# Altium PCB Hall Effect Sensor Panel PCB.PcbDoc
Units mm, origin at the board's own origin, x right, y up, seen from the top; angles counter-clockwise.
Board outline 358 x 45 mm, 2 copper layers (Top Layer, Bottom Layer); 37 components, 42 nets, 131 pads, 19 vias.
Unrouted connection lines stored in the file: 1.
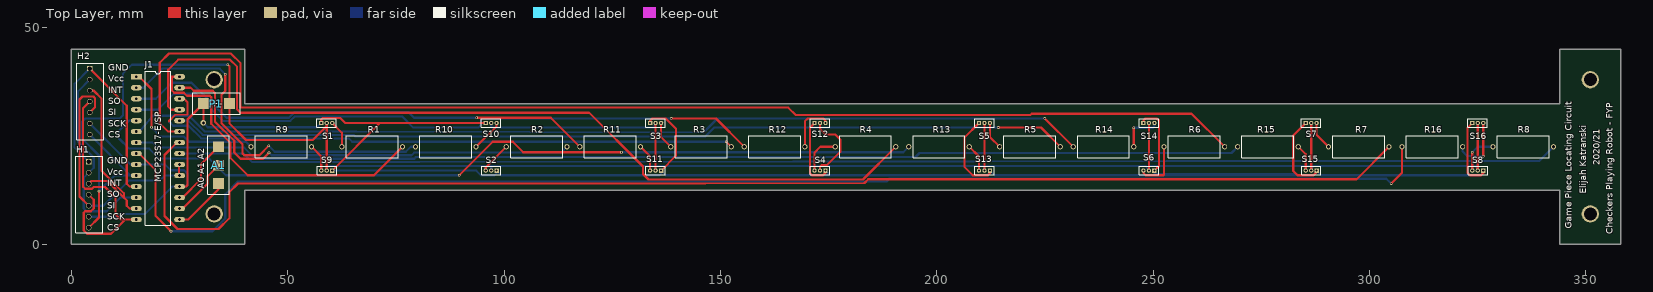
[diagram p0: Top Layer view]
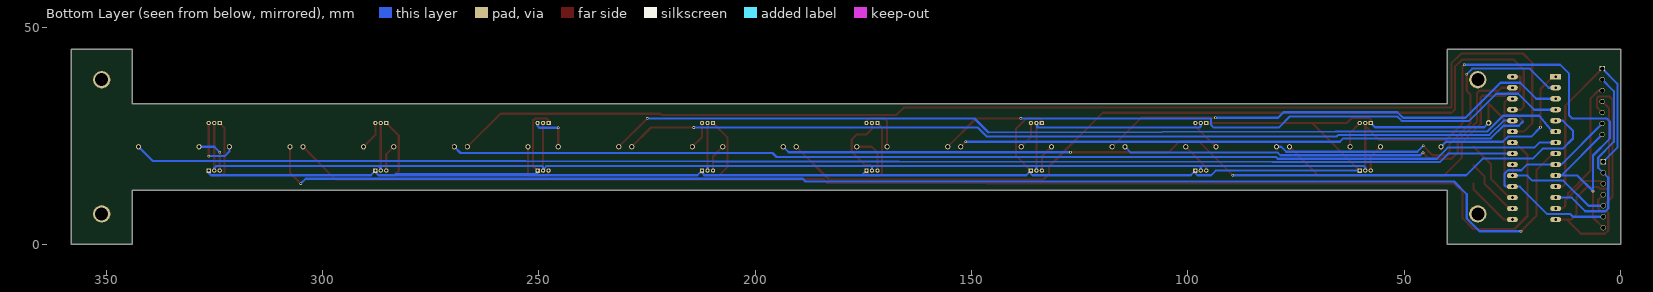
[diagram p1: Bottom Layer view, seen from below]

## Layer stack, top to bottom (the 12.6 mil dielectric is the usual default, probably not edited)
Top Solder: solder mask 0.0102, Solder Resist, Dk 3.5
Top Layer: signal copper 0.0356
Dielectric 1: dielectric 0.32, FR-4, Dk 4.8
Bottom Layer: signal copper 0.0356
Bottom Solder: solder mask 0.0102, Solder Resist, Dk 3.5

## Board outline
344,32.5 344,45 358,45 358,0 344,0 344,12.5 40,12.5 40,0 0,0 0,45 40,45 40,32.5

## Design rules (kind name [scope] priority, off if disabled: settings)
Clearance [All] p1: gap=0.13 ignorepadtopadclearanceinfootprint=FALSE
PolygonConnect [All] p1: connectstyle=Relief reliefconductorwidth=0.254 reliefentries=4 polygonreliefangle="90 Angle" airgapwidth=0.254
RoutingVias [All] p1: holewidth=0.3 width=0.6 viastyle="Through Hole" minholewidth=0.3 minwidth=0.6 maxholewidth=0.3 maxwidth=0.6
SolderMaskExpansion [All] p1: expansion=0.102 istentingtop=FALSE
Width [All] p1: maxlimit=1 minlimit=0.3 preferedwidth=0.5
30 further rules are at their usual default settings.

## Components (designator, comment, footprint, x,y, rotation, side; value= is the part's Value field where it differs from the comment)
A1 "Address" ADDRESS 34,17 r90 top
H1 "1x7 Header" MOLEX 4,19.04 r0 top
H2 "1x7 Header" MOLEX 4.24,40.58 r0 top
J1 "16-Bit I/O Expander" MCP23S17-E/SP 15,38.7 r0 top
P1 "Power" POWER 33.5,32.5 r0 top
R1 "4k7R" CFR100J4K7 76.5,22.5 r180 top
R2 "4k7R" CFR100J4K7 114.5,22.5 r180 top
R3 "4k7R" CFR100J4K7 152.5,22.5 r180 top
R4 "4k7R" CFR100J4K7 190.5,22.5 r180 top
R5 "4k7R" CFR100J4K7 228.5,22.5 r180 top
R6 "4k7R" CFR100J4K7 266.5,22.5 r180 top
R7 "4k7R" CFR100J4K7 304.5,22.5 r180 top
R8 "4k7R" CFR100J4K7 342.5,22.5 r180 top
R9 "4k7R" CFR100J4K7 55.5,22.5 r180 top
R10 "4k7R" CFR100J4K7 93.5,22.5 r180 top
R11 "4k7R" CFR100J4K7 131.5,22.5 r180 top
R12 "4k7R" CFR100J4K7 169.5,22.5 r180 top
R13 "4k7R" CFR100J4K7 207.5,22.5 r180 top
R14 "4k7R" CFR100J4K7 245.5,22.5 r180 top
R15 "4k7R" CFR100J4K7 283.5,22.5 r180 top
R16 "4k7R" CFR100J4K7 321.5,22.5 r180 top
S1 "Hall Effect Sensor" A1104EUA-T 57.73,28 r90 top
S2 "Hall Effect Sensor" A1104EUA-T 98.27,17 r270 top
S3 "Hall Effect Sensor" A1104EUA-T 133.73,28 r90 top
S4 "Hall Effect Sensor" A1104EUA-T 174.27,17 r270 top
S5 "Hall Effect Sensor" A1104EUA-T 209.73,28 r90 top
S6 "Hall Effect Sensor" A1104EUA-T 250.27,17 r270 top
S7 "Hall Effect Sensor" A1104EUA-T 285.23,28 r90 top
S8 "Hall Effect Sensor" A1104EUA-T 326.27,17 r270 top
S9 "Hall Effect Sensor" A1104EUA-T 60.27,17 r270 top
S10 "Hall Effect Sensor" A1104EUA-T 95.73,28 r90 top
S11 "Hall Effect Sensor" A1104EUA-T 136.27,17 r270 top
S12 "Hall Effect Sensor" A1104EUA-T 171.73,28 r90 top
S13 "Hall Effect Sensor" A1104EUA-T 212.27,17 r270 top
S14 "Hall Effect Sensor" A1104EUA-T 247.73,28 r90 top
S15 "Hall Effect Sensor" A1104EUA-T 287.77,17 r270 top
S16 "Hall Effect Sensor" A1104EUA-T 323.73,28 r90 top

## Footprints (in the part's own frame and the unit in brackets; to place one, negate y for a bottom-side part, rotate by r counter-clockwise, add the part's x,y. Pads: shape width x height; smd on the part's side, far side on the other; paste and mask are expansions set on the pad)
A1104EUA-T [mm]
  rect 1x1 hole 0.5: 1(0,0)
  round 1 hole 0.5: 2(0,-1.27) 3(0,-2.54)
  silkscreen extent -1,-3.5 1,1
ADDRESS [mm]
  rect 2.5x2.5 smd: 1(-3,0) 2(1.25,0) 3(5.5,0)
  silkscreen extent -5.5,-2.5 8,2.5
CFR100J4K7 [mm]
  round 1.2 hole 0.76: 1(0,0) 2(14,0)
  silkscreen extent 1,-2.5 13,2.5
MCP23S17-E/SP [mm]
  rect 2.5x1.2 hole 0.65: 1(0,0)
  oval 2.5x1.2 hole 0.65: 2(0,-2.54) 3(0,-5.08) 4(0,-7.62) 5(0,-10.16) 6(0,-12.7) 7(0,-15.24) 8(0,-17.78) 9(0,-20.32) 10(0,-22.86) 11(0,-25.4) 12(0,-27.94) 13(0,-30.48) 14(0,-33.02) 15(10,-33.02) 16(10,-30.48) 17(10,-27.94) 18(10,-25.4) 19(10,-22.86) 20(10,-20.32) 21(10,-17.78) 22(10,-15.24) 23(10,-12.7) 24(10,-10.16) 25(10,-7.62) 26(10,-5.08) 27(10,-2.54) 28(10,0)
  silkscreen extent 2.09,-34.29 7.92,1.27
MOLEX [mm]
  rect 1.2x1.2 hole 1.02: 1(0,0)
  round 1.2 hole 1.02: 2(0,-2.54) 3(0,-5.08) 4(0,-7.62) 5(0,-10.16) 6(0,-12.7) 7(0,-15.24)
  silkscreen extent -3.02,-16.4 3.22,1.23
POWER [mm]
  rect 2.5x2.5 smd: 1(-3,0) 2(3,0)
  silkscreen extent -5.5,-2.5 5.5,2.5

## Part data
H1 H2: library part 22-23-2071, "CONN HEADER VERT 7POS 2.54MM", Color=White, Contact Resistance=10mR, Current Rating=4A, Flammability Rating="UL94 V-0", Insulation Resistance=500GR, Manufacturer=Molex, Max Current Rating=10A, Max Operating Temperature=75°C, Max Voltage Rating (AC)=250V, Min Operating Temperature=0°C, Package Quantity=4000, Supplier Part Number 1=6795603P
J1: library part MCP23S17-E/SP, "TE CONNECTIVITY         CFR100J4K7             Through Hole Resistor, 4.7 kohm, 500 V, Axial Leaded, 1 W,  5%, CFR Series", Case/Package=PDIP, Frequency=10MHz, Manufacturer=Microchip, Max Operating Temperature=125°C, Max Supply Voltage=5.5V, Min Operating Temperature=-40°C, Min Supply Voltage=1.8V, Nominal Supply Current=1mA, Supplier Part Number 1=9126833
R1 R2 R3 R4 R5 R6 R7 R8 R9 R10 R11 R12 R13 R14 R15 R16: library part CFR100J4K7, "TE CONNECTIVITY         CFR100J4K7             Through Hole Resistor, 4.7 kohm, 500 V, Axial Leaded, 1 W,  5%, CFR Series", Case/Package=Conformal, Manufacturer="TE Connectivity", Max Operating Temperature=155°C, Min Operating Temperature=-55°C, Number of Resistors=1, Power Rating=1W, Resistance=4.7kR, Resistor Type="Thin Film", Supplier Part Number 1=0131873, Temperature Coefficient=0ppm/°C, Tolerance=5%, Voltage Rating=500V
S1 S2 S3 S4 S5 S6 S7 S8 S9 S10 S11 S12 S13 S14 S15 S16: library part A1104EUA-T, "ALLEGRO MICROSYSTEMS - A1104EUA-T - IC, HALL-EFFECT SWITCH SIP-3", Case/Package=SIP, Manufacturer="Allegro MicroSystems", Max Operating Temperature=85°C, Max Output Current=25mA, Max Supply Current=7.5mA, Max Supply Voltage=24V, Min Operating Temperature=-40°C, Min Supply Voltage=3.8V, Package Quantity=4000, Supplier Part Number 1=6807488

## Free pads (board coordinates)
  round 4 hole 3: 1(33,38) 2(33,7) 3(351,38) 4(351,7)

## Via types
v1: diameter 0.6, hole 0.3, Top Layer to Bottom Layer, 18 vias
v2: diameter 1.27, hole 0.711, Top Layer to Bottom Layer, 1 vias

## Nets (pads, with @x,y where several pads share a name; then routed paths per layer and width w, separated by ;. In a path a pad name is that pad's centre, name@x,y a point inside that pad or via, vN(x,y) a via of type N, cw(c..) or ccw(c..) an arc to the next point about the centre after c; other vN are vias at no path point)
GND: H1.7 H2.7 J1.10 P1.2 S1.2 S2.2 S3.2 S4.2 S5.2 S6.2 S7.2 S8.2 S9.2 S10.2 S11.2 S12.2 S13.2 S14.2 S15.2 S16.2 | length 531.9
  Top Layer w0.5: H1.7 6.375,6.175 v1(6.375,12.268) ; v1(36.144,41.478) 36.5,41.122 P1.2 36.5,27.929 40.35,24.079 55.774,24.079 59,27.305 ; S9.2 59,27.305 ; S1.2 59,27.305 ; S11.2 S3.2 ; S4.2 173,17.908 173.355,18.263 174.574,18.263 177.673,21.361 177.673,24.181 176.53,25.324 174.346,25.324 173,26.67 S12.2 ; S13.2 S5.2 ; S6.2 S14.2 ; S15.2 S7.2 ; S8.2 S16.2
  Bottom Layer w0.5: H2.7 13.74,15.84 ; J1.10 13.74,15.84 ; v1(36.144,41.478) 13.97,41.478 11.887,39.395 11.887,29.718 11.199,29.03 3.175,29.03 2.495,28.35 2.495,24.383 6.375,20.502 v1(6.375,12.268) 9.947,15.84 13.74,15.84 ; S9.2 59,17.687 59.372,18.059 97,18.059 ; S2.2 97,18.059 ; S10.2 97,27.181 97.231,26.949 134.798,26.949 134.798,27.798 S3.2 ; S11.2 135,18.059 ; S4.2 173,18.059 ; S13.2 210.959,17.087 210.959,18.059 ; S15.2 286.5,17.539 287.02,18.059 ; S8.2 325,17.544 324.485,18.059 287.02,18.059 ; 97,18.059 135,18.059 ; 135,18.059 173,18.059 ; 173,18.059 210.959,18.059 ; 210.959,18.059 248.285,18.059 S6.2 249,17.86 249.199,18.059 287.02,18.059
NetA1_1: A1.1 J1.15 | length 13.2
  Top Layer w0.5: J1.15 26.98,5.68 34,12.7 A1.1
NetA1_2: A1.2 J1.16 | length 14.1
  Top Layer w0.5: J1.16 25.654,8.22 31.471,14.037 31.471,15.721 A1.2
NetA1_3: A1.3 J1.17 | length 15.9
  Top Layer w0.5: J1.17 25.654,10.76 29.921,15.027 29.921,18.421 A1.3
NetH1_1: H1.1 H2.1 J1.11 | length 57
  Top Layer w0.5: H2.1 12.802,32.018 12.802,13.97 13.472,13.3 J1.11
  Bottom Layer w0.5: H1.1 0.737,22.303 0.737,37.077 H2.1
NetH1_2: H1.2 H2.2 J1.12 | length 47.1
  Bottom Layer w0.5: H2.2 1.549,35.349 1.549,23.647 5.156,20.041 5.156,17.656 H1.2 2.845,15.345 2.845,8.255 3.48,7.62 8.153,7.62 11.293,10.76 J1.12
NetH1_3: H1.3 H2.3 J1.13 | length 43.1
  Top Layer w0.5: H1.3 4.62,14.58 8.331,14.58 12.116,10.795 ; H2.3 5.08,35.5 6.985,33.595 6.985,16.916 12.116,11.786 12.116,10.795 ; J1.13 13.456,8.22 12.786,8.89 12.786,10.125 12.116,10.795
NetH1_4: H1.4 H2.4 J1.14 | length 60.1
  Top Layer w0.5: H1.4 5.156,10.264 5.156,8.255 4.496,7.595 3.175,7.595 2.845,7.264 2.845,3.175 3.632,2.388 9.128,2.388 12.421,5.68 ; H2.4 2.692,31.412 2.692,13.284 3.175,12.802 4.763,12.802 5.182,13.221 7.774,13.221 10.16,10.834 10.16,6.95 11.43,5.68 12.421,5.68 ; J1.14 12.421,5.68
NetH1_5: H1.5 H2.5 J1.19 J1.20 | length 60
  Top Layer w0.5: H1.5 1.88,11 1.88,33.45 2.54,34.11 5.08,34.11 5.461,33.729 5.461,31.641 H2.5 ; J1.19 24.85,15.84 24.85,18.38 J1.20
  Bottom Layer w0.5: H1.5 7.407,8.88 13.208,14.681 20.422,14.681 21.58,15.84 J1.19
NetJ1_1: J1.1 R9.2 | length 38.4
  Top Layer w0.5: J1.1 15.65,38.7 18.5,35.85 v1(18.5,27)
  Bottom Layer w0.5: v1(18.5,27) 20.65,24.85 26,24.85 27.2,23.65 40.35,23.65 R9.2
NetJ1_2: J1.2 R10.2 | length 85.7
  Top Layer w0.5: v1(35.56,39.294) 35.56,35.408 34.696,34.544 34.696,27.928 39.55,23.075 39.55,20.955 39.955,20.55 43.45,20.55 v1(45.608,22.708)
  Bottom Layer w0.5: J1.2 16.602,36.16 21.006,40.564 34.29,40.564 v1(35.56,39.294) ; v1(45.608,22.708) 46.965,21.35 77.285,21.35 78.435,22.5 R10.2
NetJ1_3: J1.3 R11.2 | length 111.2
  Top Layer w0.5: v1(93.624,29.21) 110.79,29.21 R11.2
  Bottom Layer w0.5: J1.3 19.498,33.62 23.19,37.313 27.737,37.313 35.839,29.21 50.286,29.21 51.576,30.5 77.888,30.5 79.178,29.21 v1(93.624,29.21)
NetJ1_4: J1.4 R12.2 | length 150.6
  Top Layer w0.5: v1(138.608,29.058) 148.942,29.058 R12.2
  Bottom Layer w0.5: J1.4 19.98,31.08 23.67,34.77 28.73,34.77 35,28.5 50.578,28.5 51.578,29.5 76.438,29.5 79.009,26.929 94.01,26.929 94.666,27.584 94.666,29.058 v1(138.608,29.058)
NetJ1_5: J1.5 R13.2 | length 197.5
  Top Layer w0.5: v1(89.637,15.926) 97.384,23.673 101.981,23.673 104.419,21.234 v1(127.127,21.234)
  Bottom Layer w0.5: J1.5 13.335,28.54 11,26.205 11,24.408 13.335,22.073 18.009,22.073 20.32,19.761 31.852,19.761 35.687,15.926 v1(89.637,15.926) ; v1(127.127,21.234) 192.234,21.234 R13.2
NetJ1_6: J1.6 R14.2 | length 223.8
  Top Layer w0.5: v1(224.942,29.058) R14.2
  Bottom Layer w0.5: J1.6 15.723,26 18.771,29.693 27.153,29.693 30.795,26.05 65.806,26.05 146.05,25.806 149.301,29.058 v1(224.942,29.058)
NetJ1_7: J1.7 R15.2 | length 257.2
  Bottom Layer w0.5: J1.7 18.762,23.46 19.921,22.301 39.929,22.301 42.48,19.75 79.25,19.75 79.642,20.142 195.042,20.142 195.982,21.082 268.082,21.082 R15.2
NetJ1_8: J1.8 R16.2 | length 321.9
  Top Layer w0.5: J1.8 15.65,20.92 19.392,17.178 19.392,6.608 v1(23,3) ; v1(305,14) 307.5,16.5 R16.2
  Bottom Layer w0.5: v1(23,3) 32.606,3 35.55,5.944 35.55,11.55 38.5,14.5 188.374,14.5 189,15.126 303.874,15.126 v1(305,14)
NetJ1_21: J1.21 R8.1 | length 319.7
  Bottom Layer w0.5: J1.21 39.82,20.92 41.79,18.95 80.382,18.95 339.279,19.279 R8.1
NetJ1_22: J1.22 R7.1 | length 314.4
  Top Layer w0.5: J1.22 24.35,23.46 21.5,20.61 21.5,6.5 24.5,3.5 34,3.5 36.5,6 36.5,12 38.5,14 146.5,14 183.267,14.135 184.131,15 297,15 R7.1
NetJ1_23: J1.23 R6.1 | length 281.4
  Top Layer w0.5: J1.23 22.362,26 20.422,27.94 20.422,41.91 22.555,44.044 36.83,44.044 39.1,41.774 39.1,31.572 111.125,31.572 111.15,31.547 165.659,31.547 167.335,29.87 221.64,29.87 221.92,30.15 258.85,30.15 R6.1
NetJ1_24: J1.24 R5.1 | length 207.7
  Top Layer w0.5: v1(214.198,26.949) 224.051,26.949 R5.1
  Bottom Layer w0.5: J1.24 27.026,28.54 30.316,25.25 65.25,25.25 65.633,24.867 146.507,24.867 148.59,26.949 v1(214.198,26.949)
NetJ1_25: J1.25 R4.1 | length 201.9
  Top Layer w0.5: J1.25 23.089,31.08 22.377,31.791 22.377,40.335 24.689,42.647 36.627,42.647 38.3,40.973 38.3,31.115 39.037,30.378 119.634,30.378 132.08,17.932 132.08,16.205 133.35,14.935 182.935,14.935 R4.1
NetJ1_26: J1.26 R3.1 | length 142.3
  Top Layer w0.5: 22.543,28.334 22.543,28.461 23.901,29.82 26.8,29.947 26.8,32.855 26.035,33.62 J1.26 ; v1(151.327,23.673) R3.1
  Bottom Layer w0.5: 22.543,28.334 23.495,27.381 27.053,27.381 29.984,24.45 64.085,24.45 64.862,23.673 v1(151.327,23.673)
NetJ1_27: J1.27 R2.1 | length 103.4
  Top Layer w0.5: J1.27 27.543,36.16 28.245,35.458 32.639,35.458 33.198,34.9 33.198,28.296 37.611,23.882 37.611,21.192 39.052,19.75 44.25,19.75 v1(45.658,21.158)
  Bottom Layer w0.5: v1(45.658,21.158) 46.266,20.55 78.617,20.55 79.225,21.158 113.158,21.158 R2.1
NetJ1_28: J1.28 R1.1 | length 74.8
  Top Layer w0.5: J1.28 23.19,38.7 23.19,35.56 23.749,35.001 25.984,35.001 26.67,34.315 31.966,34.315 32.321,33.961 32.321,27.801 36.696,23.426 36.696,19.948 40.718,15.926 69.926,15.926 R1.1
NetR1_2: R1.2 S1.3 | length 6.4
  Top Layer w0.5: S1.3 62.5,25.77 R1.2
NetR2_2: R2.2 S2.3 | length 7.5
  Top Layer w0.5: S2.3 95.73,17.73 R2.2
NetR3_2: R3.2 S3.3 | length 6.4
  Top Layer w0.5: S3.3 136.27,24.73 R3.2
NetR4_2: R4.2 S4.3 | length 9.5
  Top Layer w0.5: S4.3 171.73,21.159 173.071,22.5 R4.2
NetR5_2: R5.2 S5.3 | length 6.4
  Top Layer w0.5: S5.3 212.27,24.73 R5.2
NetR6_2: R6.2 S6.3 | length 12
  Top Layer w0.5: S6.3 247.73,16.481 248.285,15.926 252.324,15.926 252.5,16.102 R6.2
NetR7_2: R7.2 S7.3 | length 6.6
  Top Layer w0.5: S7.3 287.77,25.23 R7.2
NetR8_2: R8.2 S8.3 | length 9.5
  Top Layer w0.5: S8.3 v1(323.73,21.216)
  Bottom Layer w0.5: v1(323.73,21.216) 325.014,22.5 R8.2
NetR9_1: R9.1 S9.3 | length 6.4
  Top Layer w0.5: R9.1 57.73,20.27 S9.3
NetR10_1: R10.1 S10.3 | length 7.5
  Top Layer w0.5: R10.1 98.27,27.27 S10.3
NetR11_1: R11.1 S11.3 | length 6.4
  Top Layer w0.5: R11.1 133.73,20.27 S11.3
NetR12_1: R12.1 S12.3 | length 11.7
  Top Layer w0.5: R12.1 169.5,28.378 170.18,29.058 173.711,29.058 174.27,28.498 S12.3
NetR13_1: R13.1 S13.3 | length 6.4
  Top Layer w0.5: R13.1 209.73,20.27 S13.3
NetR14_1: R14.1 S14.3 | length 10
  Top Layer w0.5: R14.1 v1(245.5,26.899)
  Bottom Layer w0.5: v1(245.5,26.899) 249.873,26.899 250.27,27.296 S14.3
NetR15_1: R15.1 S15.3 | length 6.2
  Top Layer w0.5: R15.1 285.23,20.77 S15.3
NetR16_1: R16.1 S16.3 | length 13.9
  Top Layer w0.5: v1(326.27,20.345) S16.3
  Bottom Layer w0.5: R16.1 321.5,21.425 322.58,20.345 v1(326.27,20.345)
Vcc: H1.6 H2.6 J1.9 J1.18 P1.1 S1.1 S2.1 S3.1 S4.1 S5.1 S6.1 S7.1 S8.1 S9.1 S10.1 S11.1 S12.1 S13.1 S14.1 S15.1 S16.1 | length 579.6
  Top Layer w0.5: J1.18 26.47,13.3 26.822,13.652 26.822,28.822 P1.1 v2(30.5,28) ; S1.1 57.73,28.812 58.102,29.185 62.078,29.185 63.262,28 71.27,28 ; S9.1 71.27,28 ; S10.1 71.27,28 ; S3.1 133.73,28.523 134.264,29.058 137.338,29.058 139.675,26.721 139.675,20.405 S11.1 ; S12.1 170.663,26.933 170.663,16.396 171.132,15.926 173.672,15.926 174.27,16.523 S4.1 ; S5.1 206.35,24.62 206.35,17.856 208.28,15.926 211.772,15.926 212.27,16.423 S13.1 ; S14.1 247.73,28.575 248.213,29.058 250.85,29.058 251.333,28.575 251.333,18.063 S6.1 ; S7.1 282.346,25.116 282.346,16.916 283.337,15.926 287.02,15.926 287.553,16.459 287.553,16.783 S15.1 ; S16.1 322.656,26.926 322.656,16.485 323.215,15.926 325.755,15.926 326.27,16.441 S8.1
  Bottom Layer w0.5: H1.6 10.988,6.34 11.582,6.934 16.916,6.934 23.282,13.3 J1.18 26.47,13.3 26.822,13.652 26.822,16.307 26.035,17.094 22.936,17.094 21.65,18.38 J1.9 13.74,18.38 H2.6 ; v2(30.5,28) 31.5,27 56.73,27 S1.1 ; S9.1 93.541,17 94.615,15.926 97.79,15.926 98.27,16.406 S2.1 99.344,15.926 135.89,15.926 136.27,16.306 S11.1 137.344,15.926 175.344,15.926 ; S4.1 175.344,15.926 ; S6.1 250.27,16.205 283.058,16.205 283.337,15.926 ; S8.1 326.27,16.441 325.755,15.926 288.844,15.926 S15.1 287.553,16.783 287.553,16.459 287.02,15.926 283.337,15.926 ; 175.344,15.926 211.772,15.926 S13.1 213.344,15.926 283.337,15.926

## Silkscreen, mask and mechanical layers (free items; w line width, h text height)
Top Overlay:
  text "2020/21" at 353.246,18.254 h1.52 r90
  text "Elijah Katranski" at 350.074,11.649 h1.52 r90
  text "Game Piece Locating Circuit" at 346.738,3.524 h1.52 r90
  text "Checkers Playing Robot - FYP" at 356.238,2.254 h1.52 r90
